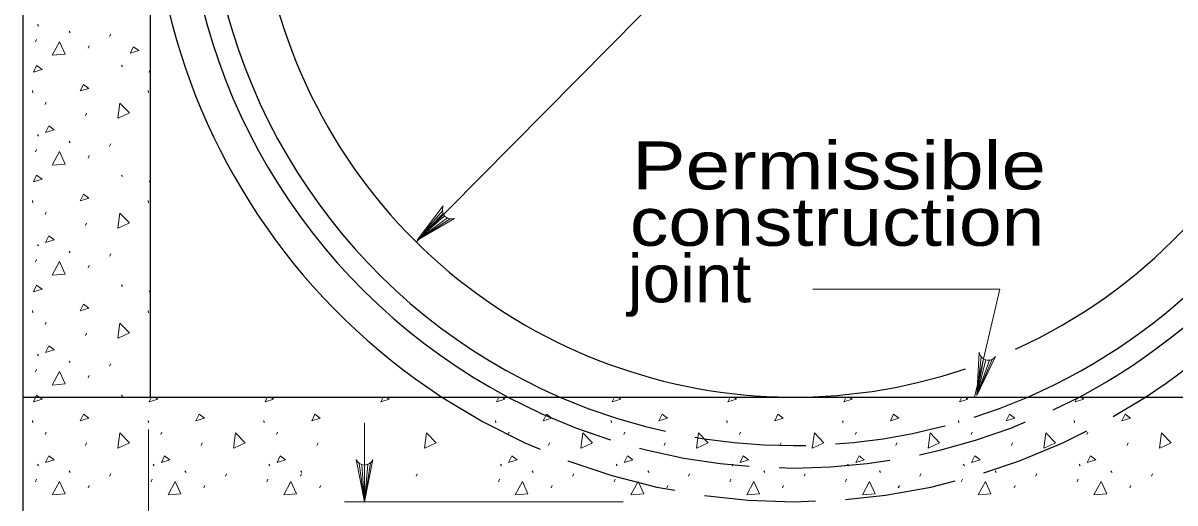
# Model space of a CAD drawing. Extents: x 1073.4 to 1107.4, y 719.4 to 741.4.
# Drawn here: x 1087.266 to 1091.113, y 723.691 to 725.295 of the extents above; entities that cross this region are included whole.
import ezdxf

# ---------------------------------------------------------------- set-up
doc = ezdxf.new("R2010")
doc.units = 0
doc.header["$LTSCALE"] = 0.062
doc.linetypes.add('LONG_DASHED', pattern=[7.5, 6, -1.5])
doc.layers.add('1', color=7, linetype='Continuous', lineweight=13)

msp = doc.modelspace()

# ---------------------------------------------------------------- linework, layer by layer
at = {"layer": '1', "lineweight": 25}
for p, q in [((1087.69092, 728.44875), (1087.69092, 724.04508)), ((1087.26608, 724.04508), (1092.41392, 724.04508)), ((1090.18958, 723.74175), (1090.19317, 723.74975))]:
    msp.add_line(p, q, dxfattribs=at)
at = {"layer": '1'}
for p, q in [((1087.31392, 725.28983), (1087.3175, 725.2845)), ((1087.42025, 725.26725), (1087.42383, 725.262)), ((1087.30725, 725.23142), (1087.31075, 725.23942)), ((1087.55525, 725.24992), (1087.55892, 725.25792)), ((1087.48342, 725.211), (1087.487, 725.219)), ((1087.59442, 725.15408), (1087.59792, 725.14875)), ((1087.68758, 725.13108), (1087.69092, 725.13808)), ((1087.69092, 725.13217), (1087.68758, 725.13108)), ((1087.29758, 725.06908), (1087.29842, 725.06108)), ((1087.68408, 725.06908), (1087.685, 725.06108)), ((1087.33967, 725.022), (1087.34325, 725.03)), ((1087.47458, 724.98558), (1087.47817, 724.99358)), ((1087.31392, 724.9225), (1087.3175, 724.91725)), ((1087.42025, 724.9), (1087.42383, 724.89467)), ((1087.55525, 724.88258), (1087.55892, 724.89058)), ((1087.30725, 724.86408), (1087.31075, 724.87208)), ((1087.48342, 724.84367), (1087.487, 724.85167)), ((1087.59442, 724.78692), (1087.59792, 724.78158)), ((1087.68758, 724.76375), (1087.69092, 724.77075)), ((1087.69092, 724.76483), (1087.68758, 724.76375)), ((1087.29758, 724.70175), (1087.29842, 724.69375)), ((1087.68408, 724.70175), (1087.685, 724.69375)), ((1087.33967, 724.65467), (1087.34325, 724.66267)), ((1088.66658, 724.66775), (1088.58225, 724.5695)), ((1088.66917, 724.65817), (1088.58225, 724.5695)), ((1088.67417, 724.6505), (1088.58225, 724.5695)), ((1087.47458, 724.61825), (1087.47817, 724.62625)), ((1088.6835, 724.64342), (1088.58225, 724.5695)), ((1088.69267, 724.64042), (1088.58225, 724.5695)), ((1087.31392, 724.55525), (1087.3175, 724.54992)), ((1087.30725, 724.49675), (1087.31075, 724.50475)), ((1087.42025, 724.53267), (1087.42383, 724.52733)), ((1087.55525, 724.51533), (1087.55892, 724.52325)), ((1087.48342, 724.47633), (1087.487, 724.48433)), ((1087.59442, 724.41958), (1087.59792, 724.41425)), ((1087.68758, 724.39642), (1087.69092, 724.40342)), ((1087.69092, 724.3975), (1087.68758, 724.39642)), ((1087.29758, 724.33442), (1087.29842, 724.32642)), ((1087.68408, 724.33442), (1087.685, 724.32642)), ((1087.33967, 724.28733), (1087.34325, 724.29533)), ((1087.47458, 724.25092), (1087.47817, 724.25892)), ((1087.31392, 724.18792), (1087.3175, 724.18258)), ((1087.42025, 724.16533), (1087.42383, 724.16)), ((1087.55525, 724.148), (1087.55892, 724.15592)), ((1090.46625, 724.17892), (1090.45142, 724.05033)), ((1090.47375, 724.17242), (1090.45142, 724.05033)), ((1090.50325, 724.17083), (1090.45142, 724.05033)), ((1090.48225, 724.16892), (1090.45142, 724.05033)), ((1090.49392, 724.16817), (1090.45142, 724.05033)), ((1087.30725, 724.12942), (1087.31075, 724.13742)), ((1087.48342, 724.109), (1087.487, 724.117)), ((1087.59442, 724.05225), (1087.59792, 724.04692)), ((1087.68758, 724.02908), (1087.69525, 724.04508)), ((1088.07425, 724.02908), (1088.08192, 724.04508)), ((1088.46075, 724.02908), (1088.46842, 724.04508)), ((1088.84733, 724.02908), (1088.855, 724.04508)), ((1089.23392, 724.02908), (1089.24158, 724.04508)), ((1089.62058, 724.02908), (1089.62825, 724.04508)), ((1090.00717, 724.02908), (1090.01475, 724.04508)), ((1090.39367, 724.02908), (1090.40133, 724.04508)), ((1090.78033, 724.02908), (1090.78792, 724.04508)), ((1087.29758, 723.96708), (1087.29842, 723.95908)), ((1087.68408, 723.96708), (1087.685, 723.95908)), ((1088.07075, 723.96708), (1088.07158, 723.95908)), ((1088.40642, 723.69525), (1088.40642, 723.95867)), ((1088.84392, 723.96708), (1088.84475, 723.95908)), ((1089.2305, 723.96708), (1089.23142, 723.95908)), ((1089.61708, 723.96708), (1089.61792, 723.95908)), ((1090.00367, 723.96708), (1090.00458, 723.95908)), ((1090.39025, 723.96708), (1090.39108, 723.95908)), ((1090.77692, 723.96708), (1090.77775, 723.95908)), ((1087.33967, 723.92), (1087.34325, 723.928)), ((1087.68458, 722.7255), (1087.68458, 723.93633)), ((1087.72625, 723.92), (1087.72983, 723.928)), ((1088.11283, 723.92), (1088.11633, 723.928)), ((1088.886, 723.92), (1088.88958, 723.928)), ((1089.27258, 723.92), (1089.27617, 723.928)), ((1089.65925, 723.92), (1089.66267, 723.928)), ((1090.04583, 723.92), (1090.04933, 723.928)), ((1090.43233, 723.92), (1090.43592, 723.928)), ((1090.81892, 723.92), (1090.8225, 723.928)), ((1087.47458, 723.88358), (1087.47817, 723.89158)), ((1087.86117, 723.88358), (1087.86467, 723.89158)), ((1088.24767, 723.88358), (1088.25125, 723.89158)), ((1089.02092, 723.88358), (1089.0245, 723.89158)), ((1089.4075, 723.88358), (1089.411, 723.89158)), ((1089.79417, 723.88358), (1089.79767, 723.89158)), ((1090.18067, 723.88358), (1090.18425, 723.89158)), ((1090.56725, 723.88358), (1090.57083, 723.89158)), ((1090.95383, 723.88358), (1090.95742, 723.89158)), ((1087.31392, 723.82058), (1087.3175, 723.81525)), ((1087.7005, 723.82058), (1087.70408, 723.81525)), ((1088.08717, 723.82058), (1088.09067, 723.81525)), ((1088.3885, 723.82342), (1088.40642, 723.69525)), ((1088.39733, 723.81908), (1088.40642, 723.69525)), ((1088.42625, 723.825), (1088.40642, 723.69525)), ((1088.41792, 723.82008), (1088.40642, 723.69525)), ((1088.40642, 723.81775), (1088.40642, 723.69525)), ((1088.86025, 723.82058), (1088.86383, 723.81525)), ((1089.24692, 723.82058), (1089.25042, 723.81525)), ((1089.6335, 723.82058), (1089.63708, 723.81525)), ((1090.02008, 723.82058), (1090.02358, 723.81525)), ((1090.40658, 723.82058), (1090.41025, 723.81525)), ((1090.79325, 723.82058), (1090.79675, 723.81525)), ((1087.30725, 723.76208), (1087.31075, 723.77008)), ((1087.42025, 723.798), (1087.42383, 723.79267)), ((1087.55525, 723.78067), (1087.55892, 723.78867)), ((1087.69375, 723.76208), (1087.69733, 723.77008)), ((1087.80692, 723.798), (1087.81042, 723.79267)), ((1087.94192, 723.78067), (1087.9455, 723.78867)), ((1088.08042, 723.76208), (1088.08392, 723.77008)), ((1088.19292, 723.78067), (1088.19642, 723.78867)), ((1088.1935, 723.798), (1088.197, 723.79267)), ((1088.57942, 723.78067), (1088.583, 723.78867)), ((1088.85358, 723.76208), (1088.85708, 723.77008)), ((1088.96658, 723.798), (1088.97017, 723.79267)), ((1089.10167, 723.78067), (1089.10525, 723.78867)), ((1089.24017, 723.76208), (1089.24367, 723.77008)), ((1089.35325, 723.798), (1089.35683, 723.79267)), ((1089.48825, 723.78067), (1089.49192, 723.78867)), ((1089.62675, 723.76208), (1089.63033, 723.77008)), ((1089.73983, 723.798), (1089.74333, 723.79267)), ((1089.87492, 723.78067), (1089.87842, 723.78867)), ((1090.01333, 723.76208), (1090.01692, 723.77008)), ((1090.12642, 723.798), (1090.12992, 723.79267)), ((1090.26142, 723.78067), (1090.265, 723.78867)), ((1090.39992, 723.76208), (1090.4035, 723.77008)), ((1090.51292, 723.798), (1090.5165, 723.79267)), ((1090.64808, 723.78067), (1090.65158, 723.78867)), ((1090.78658, 723.76208), (1090.79008, 723.77008)), ((1090.89958, 723.798), (1090.90317, 723.79267)), ((1091.03458, 723.78067), (1091.03825, 723.78867)), ((1087.48342, 723.74175), (1087.487, 723.74975)), ((1087.87, 723.74175), (1087.87358, 723.74975)), ((1088.25658, 723.74175), (1088.26017, 723.74975)), ((1089.02983, 723.74175), (1089.03333, 723.74975)), ((1089.41633, 723.74175), (1089.41992, 723.74975)), ((1089.803, 723.74175), (1089.8065, 723.74975)), ((1090.57617, 723.74175), (1090.57967, 723.74975)), ((1090.96267, 723.74175), (1090.96625, 723.74975)), ((1088.33983, 723.69525), (1088.47308, 723.69525)), ((1089.27067, 723.69525), (1088.34933, 723.69525))]:
    msp.add_line(p, q, dxfattribs=at)
at = {"layer": '1', "lineweight": 25}
msp.add_lwpolyline([(1092.41392, 723.54533), (1087.26608, 723.54533), (1087.26608, 728.54242)], dxfattribs=at)
at = {"layer": '1'}
for points in [[(1088.57933, 724.56308), (1090.19025, 726.19175), (1091.10083, 727.11242)], [(1087.36358, 725.187), (1087.38758, 725.23233), (1087.40625, 725.19058), (1087.36458, 725.187)], [(1087.58258, 724.97642), (1087.58958, 725.02708), (1087.62133, 724.99425), (1087.58333, 724.97667)], [(1087.36358, 724.81967), (1087.38758, 724.865), (1087.40625, 724.82325), (1087.36458, 724.81967)], [(1087.58258, 724.60908), (1087.58958, 724.65975), (1087.62133, 724.627), (1087.58333, 724.60933)], [(1088.70725, 724.64183), (1088.58225, 724.5695), (1088.66975, 724.68442)], [(1087.36358, 724.45242), (1087.38758, 724.49767), (1087.40625, 724.45592), (1087.36458, 724.45242)], [(1090.4435, 724.04508), (1090.52875, 724.4055), (1089.90358, 724.4055)], [(1087.58258, 724.24175), (1087.58958, 724.29242), (1087.62133, 724.25967), (1087.58333, 724.242)], [(1090.51442, 724.18025), (1090.45142, 724.05033), (1090.45958, 724.19442)], [(1087.36358, 724.08508), (1087.38758, 724.13033), (1087.40625, 724.08867), (1087.36458, 724.08508)], [(1087.70658, 724.04508), (1087.71592, 724.038), (1087.68758, 724.02908)], [(1088.09325, 724.04508), (1088.10258, 724.038), (1088.07425, 724.02908)], [(1088.47975, 724.04508), (1088.48925, 724.038), (1088.46075, 724.02908)], [(1088.86633, 724.04508), (1088.87575, 724.038), (1088.84733, 724.02908)], [(1089.25292, 724.04508), (1089.26233, 724.038), (1089.23392, 724.02908)], [(1089.63958, 724.04508), (1089.64892, 724.038), (1089.62058, 724.02908)], [(1090.02608, 724.04508), (1090.03558, 724.038), (1090.00717, 724.02908)], [(1090.41267, 724.04508), (1090.42208, 724.038), (1090.39367, 724.02908)], [(1090.79925, 724.04508), (1090.80867, 724.038), (1090.78033, 724.02908)], [(1087.58258, 723.87442), (1087.58958, 723.92508), (1087.62133, 723.89233), (1087.58333, 723.87467)], [(1087.96908, 723.87442), (1087.97617, 723.92508), (1088.00792, 723.89233), (1087.96992, 723.87467)], [(1088.60667, 723.87442), (1088.61367, 723.92508), (1088.6455, 723.89233), (1088.6075, 723.87467)], [(1089.12892, 723.87442), (1089.13592, 723.92508), (1089.16775, 723.89233), (1089.12975, 723.87467)], [(1089.51558, 723.87442), (1089.5225, 723.92508), (1089.55425, 723.89233), (1089.51633, 723.87467)], [(1089.90208, 723.87442), (1089.90917, 723.92508), (1089.94092, 723.89233), (1089.90292, 723.87467)], [(1090.28867, 723.87442), (1090.29567, 723.92508), (1090.3275, 723.89233), (1090.2895, 723.87467)], [(1090.67525, 723.87442), (1090.68225, 723.92508), (1090.71408, 723.89233), (1090.67608, 723.87467)], [(1091.06192, 723.87442), (1091.06892, 723.92508), (1091.10058, 723.89233), (1091.06267, 723.87467)], [(1088.43475, 723.83683), (1088.40642, 723.69525), (1088.37817, 723.83683)], [(1087.36358, 723.71775), (1087.38758, 723.763), (1087.40625, 723.72133), (1087.36458, 723.71775)], [(1087.75025, 723.71775), (1087.77425, 723.763), (1087.79283, 723.72133), (1087.75108, 723.71775)], [(1088.13675, 723.71775), (1088.16075, 723.763), (1088.17942, 723.72133), (1088.13767, 723.71775)], [(1088.90992, 723.71775), (1088.93392, 723.763), (1088.95258, 723.72133), (1088.91092, 723.71775)], [(1089.29658, 723.71775), (1089.32058, 723.763), (1089.33925, 723.72133), (1089.29742, 723.71775)], [(1089.68317, 723.71775), (1089.70708, 723.763), (1089.72575, 723.72133), (1089.684, 723.71775)], [(1090.06975, 723.71775), (1090.09367, 723.763), (1090.11233, 723.72133), (1090.07058, 723.71775)], [(1090.45633, 723.71775), (1090.48025, 723.763), (1090.49892, 723.72133), (1090.45725, 723.71775)], [(1090.84292, 723.71775), (1090.86692, 723.763), (1090.88558, 723.72133), (1090.84383, 723.71775)]]:
    msp.add_lwpolyline(points, dxfattribs=at)
for points in [[(1087.62425, 725.19358), (1087.63492, 725.21575), (1087.65267, 725.20242)], [(1087.301, 725.13108), (1087.31158, 725.15325), (1087.32942, 725.14)], [(1087.457, 725.06767), (1087.46758, 725.08983), (1087.48542, 725.0765)], [(1087.34142, 724.92875), (1087.35208, 724.95092), (1087.36992, 724.93758)], [(1087.301, 724.76375), (1087.31158, 724.786), (1087.32942, 724.77267)], [(1087.457, 724.70033), (1087.46758, 724.7225), (1087.48542, 724.70917)], [(1087.34142, 724.56142), (1087.35208, 724.58358), (1087.36992, 724.57025)], [(1087.301, 724.39642), (1087.31158, 724.41867), (1087.32942, 724.40533)], [(1087.457, 724.33308), (1087.46758, 724.35517), (1087.48542, 724.34183)], [(1087.34142, 724.19408), (1087.35208, 724.21633), (1087.36992, 724.203)], [(1087.301, 724.02908), (1087.31158, 724.05133), (1087.32942, 724.038)], [(1087.457, 723.96575), (1087.46758, 723.98792), (1087.48542, 723.97458)], [(1087.84358, 723.96575), (1087.85425, 723.98792), (1087.87192, 723.97458)], [(1088.23025, 723.96575), (1088.24083, 723.98792), (1088.25858, 723.97458)], [(1089.00333, 723.96575), (1089.014, 723.98792), (1089.03175, 723.97458)], [(1089.38992, 723.96575), (1089.40058, 723.98792), (1089.41833, 723.97458)], [(1089.77658, 723.96575), (1089.78725, 723.98792), (1089.80492, 723.97458)], [(1090.16308, 723.96575), (1090.17375, 723.98792), (1090.19158, 723.97458)], [(1090.54967, 723.96575), (1090.56033, 723.98792), (1090.57808, 723.97458)], [(1090.93625, 723.96575), (1090.94692, 723.98792), (1090.96467, 723.97458)], [(1087.34142, 723.82675), (1087.35208, 723.849), (1087.36992, 723.83567)], [(1087.728, 723.82675), (1087.73867, 723.849), (1087.75642, 723.83567)], [(1088.11458, 723.82675), (1088.12525, 723.849), (1088.143, 723.83567)], [(1088.88783, 723.82675), (1088.89842, 723.849), (1088.91625, 723.83567)], [(1089.27433, 723.82675), (1089.285, 723.849), (1089.30275, 723.83567)], [(1089.661, 723.82675), (1089.67158, 723.849), (1089.68933, 723.83567)], [(1090.04758, 723.82675), (1090.05825, 723.849), (1090.07592, 723.83567)], [(1090.43417, 723.82675), (1090.44483, 723.849), (1090.46258, 723.83567)], [(1090.82067, 723.82675), (1090.83133, 723.849), (1090.84917, 723.83567)]]:
    msp.add_lwpolyline(points, close=True, dxfattribs=at)
for centre, start, end in [((1088.69704, 724.6707), 153.48095, 289.30707), ((1090.48984, 724.19844), 187.54263, 323.36876), ((1088.40641, 723.84829), 202.08782, 337.91395)]:
    msp.add_arc(centre, 0.03056, start, end, dxfattribs=at)
at = {"layer": '1', "lineweight": 25}
for centre, major_axis, start_param, end_param in [((1089.84007, 725.84401), (2.03654, 0), 5.2000511, 8.308237), ((1089.8401, 725.84401), (2.14899, 0), 5.291026, 8.8932394), ((1089.8401, 725.84398), (1.96158, 0), 5.1222386, 8.2222672), ((1089.8401, 725.83775), (1.79289, 0), 5.1381757, 8.1439338), ((1089.84007, 725.84401), (2.03654, 0), 2.1491781, 4.2247268), ((1089.8401, 725.84398), (1.96158, 0), 2.1743579, 4.3025393), ((1089.8401, 725.83775), (1.79289, 0), 2.2407888, 5.0382117), ((1089.8401, 725.84401), (2.14899, 0), 2.6285244, 4.1337519)]:
    msp.add_ellipse(centre, major_axis=major_axis, ratio=0.999895, start_param=start_param, end_param=end_param, dxfattribs=at)
at = {"layer": '1', "linetype": 'LONG_DASHED', "lineweight": 25}
for centre, major_axis, start_param, end_param in [((1089.8401, 725.84401), (2.14899, 0), 4.1337519, 5.291026), ((1089.84007, 725.84401), (2.03654, 0), 4.2247268, 5.2000511), ((1089.8401, 725.84398), (1.96158, 0), 4.3025393, 5.1222386)]:
    msp.add_ellipse(centre, major_axis=major_axis, ratio=0.999895, start_param=start_param, end_param=end_param, dxfattribs=at)

# ---------------------------------------------------------------- texts
at = {"layer": '1'}
for s, width, p in [('Permissible', 1.25, (1089.3005, 724.739)), ('construction', 1.2, (1089.29308, 724.55033)), ('joint', 1.05, (1089.28567, 724.3615))]:
    msp.add_text(s, height=0.16, dxfattribs=dict(at, width=width)).set_placement(p)

doc.saveas('drawing.dxf')
